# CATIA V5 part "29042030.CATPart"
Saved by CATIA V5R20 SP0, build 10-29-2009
Part number: 29042030
Definition: NONE
Nomenclature: 29042030
Source: Unknown
Description: 29042030
Bounding box of the stored display mesh (mm): x -15 to 44.548, y -35 to 69.548, z -25 to 25
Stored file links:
  C:\Users\Utente\Desktop\IO LAVORO\3D X SITO CF\X SITO\PLASTICA\RF1\29042030.CATPart
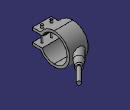
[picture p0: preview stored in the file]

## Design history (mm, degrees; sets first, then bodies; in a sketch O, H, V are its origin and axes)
Body1 "29042030" (main body)
  Solid1: solid without history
